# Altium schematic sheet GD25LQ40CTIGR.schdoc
size 127 x 101 mm
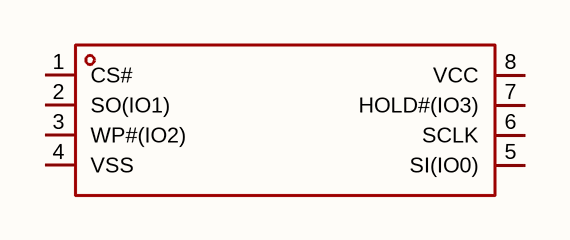
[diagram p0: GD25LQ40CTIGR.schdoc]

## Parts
U?  gd25lq40ctigr  [SOIC-8_L4.9-W3.9-P1.27-LS6.0-BL]  (value not drawn)

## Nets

Not connected (* = marked no-connect by the designer): U? 1(CS#) 2(SO(IO1)) 3(WP#(IO2)) 4(VSS) 5(SI(IO0)) 6(SCLK) 7(HOLD#(IO3)) 8(VCC)

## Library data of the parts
U? = gd25lq40ctigr: 接口类型:SPI;存储容量:4Mbit;时钟频率(fc):104MHz;; Manufacturer: GigaDevice(兆易创新); AddInBom: yes; ModelId: e81d2f7d937b4a6ab1dca543ff5d56a4; ModelName: SOIC-8_L4.9-W3.9-H1.7-LS6.0-P1.27; ModelTransform: 192.913,236.22,0,0,0,0,0,0,0; Interface: SPI; Memory Size: 4Mbit; Clock Frequency: 104MHz; Voltage - Supply: 1.65V~2.1V; Standby Supply Current: 9uA; Program / Erase Cycles: 100000次; Page Programming Time (Tpp): 700us; Data Retention - TDR (Year): 20年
